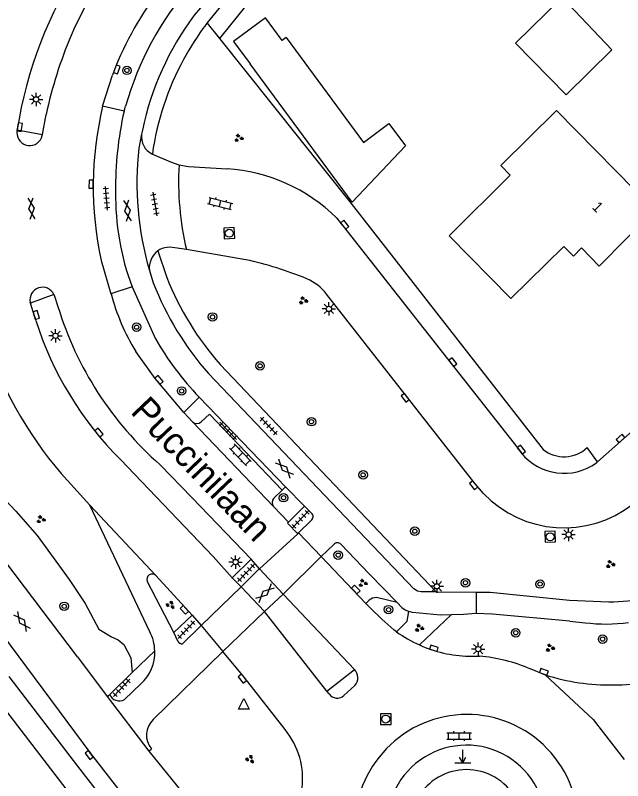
# Model space of a CAD drawing. Extents: x 137999 to 141000, y 397500 to 400501.
# Drawn here: x 138129 to 138186.2, y 398691.6 to 398763.7 of the extents above; entities that cross this region are included whole.
import ezdxf

# ---------------------------------------------------------------- set-up
doc = ezdxf.new("R2010")
doc.units = 0
for name, color, linetype in [('gg-afsc-erfafscheiding', 7, 'Continuous'), ('gg-anno-huisnummerreeks BGT', 7, 'Continuous'), ('gg-anno-openbare ruimte label', 7, 'Continuous'), ('gg-bbg-gedigitaliseerde bijgebouw', 7, 'Continuous'), ('gg-bbg-hoofdgebouw', 7, 'Continuous'), ('gg-knt-bronhoudergrens', 7, 'Continuous'), ('gg-knt-verharding', 7, 'Continuous'), ('gg-knt-verharding nz', 7, 'Continuous'), ('gt-grn-groengrens', 7, 'Continuous'), ('gt-grn-weggrens', 7, 'Continuous'), ('gt-symb-boom', 7, 'Continuous'), ('gt-symb-gesloten verharding', 7, 'Continuous'), ('gt-symb-groenvak', 7, 'Continuous'), ('gt-symb-klinker verharding', 7, 'Continuous'), ('gt-symb-kolk', 7, 'Continuous'), ('gt-symb-lichtmast', 7, 'Continuous'), ('gt-symb-markant object', 7, 'Continuous'), ('gt-symb-rioolschacht', 7, 'Continuous'), ('gt-symb-tegel verharding', 7, 'Continuous'), ('gt-symb-waterafsluiter', 7, 'Continuous')]:
    doc.layers.add(name, color=color, linetype=linetype)

# ---------------------------------------------------------------- blocks, each defined once
blk = doc.blocks.new('gt0-KOLK')
at = {"layer": 'gt-symb-kolk'}
blk.add_lwpolyline([(0, 0), (0.375, 0), (0.375, 0.4), (-0.375, 0.4), (-0.375, 0), (0, 0)], dxfattribs=at)
blk = doc.blocks.new('gt0-BOOM')
at = {"layer": 'gt-symb-boom'}
for radius in [0.4, 0.2]:
    blk.add_circle((0, 0), radius, dxfattribs=at)
blk = doc.blocks.new('gt0-LMAST')
at = {"layer": 'gt-symb-lichtmast'}
for p, q in [((-0.182, 0.173), (-0.447, 0.438)), ((-0.005, 0.246), (-0.005, 0.621)), ((0.172, 0.173), (0.437, 0.438)), ((-0.255, -0.004), (-0.63, -0.004)), ((-0.182, -0.181), (-0.447, -0.446)), ((-0.005, -0.254), (-0.005, -0.629)), ((0.437, -0.446), (0.172, -0.181)), ((0.245, -0.004), (0.62, -0.004))]:
    blk.add_line(p, q, dxfattribs=at)
blk.add_circle((-0.005, -0.004), 0.25, dxfattribs=at)
blk = doc.blocks.new('gt0-GESVH1')
at = {"layer": 'gt-symb-gesloten verharding'}
for p, q in [((-0.992, -0.261), (0.008, 0.239)), ((0.008, -0.261), (-0.992, 0.239)), ((0.008, 0.239), (1.008, -0.261)), ((1.008, 0.239), (0.008, -0.261))]:
    blk.add_line(p, q, dxfattribs=at)
blk = doc.blocks.new('gt0-TEG1')
at = {"layer": 'gt-symb-tegel verharding'}
for p, q in [((-1.125, 0), (1.125, 0)), ((-0.9, -0.25), (-0.9, 0.25)), ((-0.45, -0.25), (-0.45, 0.25)), ((0, -0.25), (0, 0.25)), ((0.45, -0.25), (0.45, 0.25)), ((0.9, -0.25), (0.9, 0.25))]:
    blk.add_line(p, q, dxfattribs=at)
blk = doc.blocks.new('gt0-KL1')
at = {"layer": 'gt-symb-klinker verharding'}
for p, q in [((-1.15, 0.3), (1.15, 0.3)), ((-1, -0.3), (-1, 0.3)), ((-0.5, 0.3), (-0.5, 0.45)), ((0, -0.3), (0, 0.3)), ((0.5, 0.3), (0.5, 0.45)), ((1, -0.3), (1, 0.3)), ((-1.15, -0.3), (1.15, -0.3)), ((-0.5, -0.45), (-0.5, -0.3)), ((0.5, -0.45), (0.5, -0.3))]:
    blk.add_line(p, q, dxfattribs=at)
blk = doc.blocks.new('gt0-RS')
at = {"layer": 'gt-symb-rioolschacht'}
blk.add_lwpolyline([(-0.5, -0.5), (0.5, -0.5), (0.5, 0.5), (-0.5, 0.5)], close=True, dxfattribs=at)
blk.add_circle((0, 0), 0.375, dxfattribs=at)
blk = doc.blocks.new('gt0-GRVAK')
at = {"layer": 'gt-symb-groenvak'}
for p, q in [((-0.11, 0.189), (-0.228, 0.24)), ((-0.182, 0.153), (0.088, 0.153)), ((-0.091, 0.211), (-0.156, 0.322)), ((-0.047, 0.214), (-0.047, 0.393)), ((-0.004, 0.211), (0.061, 0.322)), ((0.015, 0.189), (0.133, 0.24)), ((0.262, -0.052), (0.197, 0.059)), ((0.305, -0.049), (0.305, 0.13)), ((0.349, -0.052), (0.414, 0.059)), ((-0.245, -0.228), (-0.363, -0.177)), ((-0.318, -0.264), (-0.047, -0.264)), ((-0.226, -0.206), (-0.291, -0.095)), ((-0.183, -0.203), (-0.183, -0.024)), ((-0.139, -0.206), (-0.074, -0.095)), ((-0.12, -0.228), (-0.002, -0.177)), ((0.243, -0.074), (0.125, -0.023)), ((0.17, -0.11), (0.441, -0.11)), ((0.368, -0.074), (0.486, -0.023))]:
    blk.add_line(p, q, dxfattribs=at)
blk = doc.blocks.new('gt0-WAFSL')
at = {"layer": 'gt-symb-waterafsluiter'}
for p, q in [((-0.5, -0.333), (0, 0.667)), ((0, 0.667), (0.5, -0.333)), ((0.5, -0.333), (-0.5, -0.333))]:
    blk.add_line(p, q, dxfattribs=at)
blk = doc.blocks.new('gt0-MARKOB')
at = {"layer": 'gt-symb-markant object'}
for p, q in [((0, 0), (0, 1.2)), ((-0.75, 0), (0.75, 0)), ((0, 0), (-0.3, 0.52)), ((0, 0), (0.3, 0.52))]:
    blk.add_line(p, q, dxfattribs=at)

msp = doc.modelspace()

# ---------------------------------------------------------------- linework, layer by layer
at = {"layer": 'gg-afsc-erfafscheiding'}
for p, q in [((138147.036, 398762.936), (138148.205, 398761.472)), ((138139.751, 398683.118), (138127.758, 398698.679))]:
    msp.add_line(p, q, dxfattribs=at)
msp.add_lwpolyline([(138148.205, 398761.472), (138160.59, 398745.962), (138178.669, 398722.813)], dxfattribs=at)
msp.add_arc((138180.652, 398725.311), 3.19, 231.55041, 313.15167, dxfattribs=at)
at = {"layer": 'gg-bbg-gedigitaliseerde bijgebouw'}
for points in [[(138176.073, 398761.049), (138180.478, 398765.389), (138185.147, 398760.429), (138180.853, 398756.198), (138176.073, 398761.049)], [(138154.488, 398761.585), (138154.105, 398761.302), (138152.534, 398763.431), (138149.534, 398761.217), (138151.105, 398759.088)], [(138154.488, 398761.585), (138161.773, 398751.714), (138164.162, 398753.477), (138165.711, 398751.379), (138160.7, 398746.088), (138151.105, 398759.088)]]:
    msp.add_lwpolyline(points, dxfattribs=at)
at = {"layer": 'gg-bbg-hoofdgebouw'}
msp.add_lwpolyline([(138174.691, 398749.52), (138175.561, 398748.61), (138169.821, 398742.92), (138175.631, 398737.01), (138180.611, 398741.92), (138181.521, 398741), (138182.291, 398741.78), (138183.961, 398740.07), (138189.161, 398745.32), (138179.931, 398754.71), (138174.691, 398749.52)], dxfattribs=at)
at = {"layer": 'gg-knt-bronhoudergrens'}
msp.add_lwpolyline([(138178.867, 398701.608), (138183.382, 398697.392), (138186.297, 398693.634)], dxfattribs=at)
at = {"layer": 'gg-knt-verharding'}
for p, q in [((138147.036, 398762.936), (138158.71, 398777.157)), ((138146.405, 398764.369), (138145.831, 398763.67)), ((138146.939, 398762.818), (138147.036, 398762.936)), ((138138.441, 398758.882), (138138.13, 398758.048)), ((138137.202, 398755.105), (138138.13, 398758.048)), ((138139.217, 398754.64), (138137.202, 398755.105)), ((138139.217, 398754.64), (138139.361, 398755.13)), ((138131.527, 398752.458), (138131.871, 398754.323)), ((138129.14, 398752.86), (138129.145, 398752.892)), ((138129.145, 398752.892), (138131.527, 398752.458)), ((138140.951, 398752.862), (138140.868, 398752.48)), ((138131.511, 398752.37), (138131.527, 398752.458)), ((138140.868, 398752.48), (138140.619, 398751.17)), ((138130.001, 398751.46), (138130.191, 398751.42)), ((138142.387, 398741.503), (138143.231, 398738.979)), ((138145.09, 398741.62), (138144.217, 398741.738)), ((138150.682, 398740.665), (138145.09, 398741.62)), ((138137.069, 398740.601), (138137.987, 398737.466)), ((138141.601, 398739.663), (138141.971, 398738.48)), ((138139.973, 398738.111), (138137.987, 398737.466)), ((138139.973, 398738.111), (138142.135, 398733.283)), ((138132.617, 398737.397), (138130.393, 398736.582)), ((138132.651, 398737.32), (138132.991, 398736.277)), ((138130.393, 398736.582), (138130.368, 398736.661)), ((138130.901, 398734.96), (138130.393, 398736.582)), ((138200.091, 398736.162), (138183.801, 398721.645)), ((138148.251, 398730.81), (138168.611, 398709.394)), ((138144.83, 398726.288), (138146.277, 398727.74)), ((138154.421, 398719.282), (138146.277, 398727.74)), ((138134.84, 398703.296), (138116.908, 398726.868)), ((138144.83, 398726.288), (138145.646, 398725.415)), ((138145.646, 398725.415), (138153.295, 398717.425)), ((138147.592, 398712.743), (138138.876, 398721.865)), ((138142.621, 398721.37), (138145.591, 398718.273)), ((138183.801, 398721.645), (138183.69, 398721.546)), ((138133.299, 398720.532), (138135.996, 398717.562)), ((138154.088, 398718.992), (138153.327, 398718.211)), ((138154.088, 398718.992), (138154.421, 398719.282)), ((138156.216, 398717.46), (138154.421, 398719.282)), ((138151.172, 398712.474), (138145.591, 398718.273)), ((138141.641, 398705.65), (138135.996, 398717.562)), ((138154.693, 398715.97), (138153.295, 398717.425)), ((138156.216, 398717.46), (138154.693, 398715.97)), ((138156.873, 398716.818), (138156.216, 398717.46)), ((138155.655, 398714.97), (138156.83, 398716.116)), ((138155.563, 398714.88), (138155.655, 398714.97)), ((138157.785, 398712.726), (138158.957, 398713.871)), ((138147.592, 398712.743), (138149.402, 398710.74)), ((138151.172, 398712.474), (138149.402, 398710.74)), ((138151.982, 398711.571), (138151.172, 398712.474)), ((138161.996, 398708.318), (138157.785, 398712.726)), ((138143.893, 398705.587), (138141.401, 398710.406)), ((138142.214, 398710.946), (138145.624, 398707.2)), ((138149.402, 398710.74), (138150.241, 398709.863)), ((138152.452, 398707.561), (138154.193, 398709.184)), ((138154.193, 398709.184), (138160.902, 398702.106)), ((138168.611, 398709.394), (138172.369, 398709.376)), ((138158.318, 398700.062), (138152.452, 398707.561)), ((138143.893, 398705.587), (138145.624, 398707.2)), ((138145.624, 398707.2), (138146.485, 398706.25)), ((138146.485, 398706.25), (138144.718, 398704.522)), ((138181.191, 398706.636), (138182.632, 398706.5)), ((138144.287, 398704.78), (138143.893, 398705.587)), ((138142.111, 398703.851), (138139.992, 398701.801)), ((138141.949, 398697.388), (138148.517, 398703.793)), ((138134.84, 398703.296), (138137.621, 398699.553)), ((138171.659, 398703.35), (138172.67, 398703.355)), ((138139.992, 398701.801), (138137.873, 398699.75)), ((138158.318, 398700.062), (138160.902, 398702.106)), ((138177.504, 398702.145), (138178.867, 398701.608)), ((138139.253, 398699.275), (138140.787, 398700.745)), ((138160.945, 398700.588), (138159.925, 398699.638)), ((138137.621, 398699.553), (138137.873, 398699.75)), ((138158.528, 398699.794), (138158.318, 398700.062)), ((138141.554, 398694.421), (138141.792, 398694.637))]:
    msp.add_line(p, q, dxfattribs=at)
for points in [[(138141.883, 398750.614), (138143.6, 398749.879), (138144.39, 398749.587)], [(138144.39, 398749.587), (138145.279, 398749.435), (138148.915, 398749.228)], [(138159.217, 398744.601), (138159.849, 398743.83), (138170.017, 398730.902), (138176.623, 398722.475)], [(138173.053, 398718.657), (138172.291, 398719.567), (138158.293, 398737.433)], [(138144.83, 398726.288), (138142.131, 398729.49), (138140.331, 398732.03)], [(138168.611, 398709.394), (138167.191, 398709.4), (138166.831, 398709.47), (138166.501, 398709.69), (138147.169, 398729.952)], [(138154.088, 398718.992), (138147.274, 398726.133), (138146.484, 398725.407)], [(138154.693, 398715.97), (138154.611, 398715.878), (138155.563, 398714.88)], [(138164.937, 398708.396), (138162.3, 398711.113), (138159.642, 398713.881)], [(138150.241, 398709.863), (138151.873, 398711.505), (138151.982, 398711.571)], [(138172.369, 398709.376), (138173.681, 398709.37), (138181.161, 398708.61), (138184.861, 398708.47)], [(138164.881, 398705.639), (138164.629, 398705.826), (138163.499, 398706.827), (138162.415, 398707.875), (138161.996, 398708.318)], [(138164.937, 398708.396), (138165.384, 398707.936), (138165.681, 398707.718), (138166.016, 398707.552)], [(138170.026, 398707.237), (138169.018, 398707.216), (138166.372, 398707.448), (138166.016, 398707.552)], [(138172.359, 398707.368), (138171.182, 398707.261), (138170.026, 398707.237)], [(138181.191, 398706.636), (138173.898, 398707.3), (138172.359, 398707.368)], [(138127.784, 398705.356), (138136.093, 398694.176), (138143.936, 398684.05), (138144.646, 398683.101), (138144.718, 398682.997)], [(138154.383, 398696.443), (138150.514, 398701.365), (138148.517, 398703.793)], [(138141.477, 398684.453), (138134.874, 398692.99), (138128.386, 398701.442)], [(138141.554, 398694.421), (138146.299, 398688.563), (138148.875, 398686.4)]]:
    msp.add_lwpolyline(points, dxfattribs=at)
for centre, radius, start, end in [((138261.398, 398663.891), 170.81, 133.67131, 144.97275), ((138245.444, 398679.061), 150.927, 135.31184, 149.75881), ((138171.451, 398745.129), 40.78, 136.0715, 155.91278), ((138169.177, 398746.531), 40.534, 146.98222, 170.97108), ((138170.659, 398745.364), 34.939, 142.36329, 157.23873), ((138167.914, 398747.037), 29.678, 139.04988, 164.17548), ((138167.392, 398747.429), 26.993, 143.01082, 168.38917), ((138168.123, 398746.906), 26.494, 143.08779, 151.56828), ((138174.397, 398744.997), 43.537, 157.33686, 167.63041), ((138168.159, 398746.875), 26.541, 151.54838, 171.90241), ((138168.813, 398747.563), 32.498, 166.57988, 192.36936), ((138170.569, 398747.521), 32.15, 167.20732, 180.7865), ((138130.361, 398752.646), 1.24, 170.06751, 253.11552), ((138130.34, 398752.605), 1.195, 262.84726, 348.63764), ((138169.46, 398747.836), 29.033, 173.40571, 196.34983), ((138172.222, 398748.018), 27.876, 176.77379, 193.26871), ((138147.878, 398733.137), 16.124, 45.31356, 86.3133), ((138162.883, 398746.691), 24.464, 179.08985, 200.53229), ((138143.559, 398739.622), 2.216, 72.71212, 121.9231), ((138143.581, 398707.839), 33.586, 67.50138, 77.79398), ((138168.689, 398748.917), 28.684, 201.33746, 221.38896), ((138170.087, 398749.855), 28.975, 202.04764, 221.09533), ((138154.489, 398734.425), 4.849, 38.33175, 66.36749), ((138131.542, 398736.878), 1.194, 25.77146, 190.47059), ((138131.651, 398736.925), 1.075, 21.58043, 26.06809), ((138157.604, 398742.701), 20.303, 194.94294, 211.70841), ((138163.841, 398745.642), 32.241, 196.88713, 228.83822), ((138161.823, 398744.816), 32.455, 197.6791, 225.00466), ((138161.72, 398744.895), 37.434, 197.51375, 220.60438), ((138167.073, 398747.599), 28.755, 209.85835, 223.6794), ((138146.069, 398725.835), 0.596, 224.81026, 314.09582), ((138180.649, 398725.755), 5.193, 219.1744, 305.84773), ((138153.728, 398717.801), 0.574, 134.37134, 220.96593), ((138180.638, 398725.973), 10.538, 223.96857, 308.01701), ((138156.56, 398716.485), 0.457, 306.22327, 46.76635), ((138159.304, 398713.566), 0.462, 42.96262, 138.71013), ((138141.872, 398710.579), 0.502, 46.97516, 200.2096), ((138184.893, 398725.83), 17.36, 269.8932, 293.58436), ((138184.552, 398721.609), 15.23, 262.75956, 278.11345), ((138137.95, 398703.725), 4.163, 1.73792, 27.54531), ((138171.976, 398715.49), 12.14, 234.23617, 245.89959), ((138144.659, 398704.913), 0.395, 199.61403, 278.57583), ((138138.248, 398703.663), 3.868, 311.03384, 2.7918), ((138171.985, 398715.485), 12.14, 245.85119, 268.45917), ((138171.331, 398687.743), 15.669, 66.79743, 85.09662), ((138160.154, 398701.325), 1.081, 317.0051, 46.24004), ((138185.112, 398720.804), 20.163, 270.58229, 289.01327), ((138184.966, 398720.315), 19.676, 251.94248, 271.02205), ((138138.772, 398700.119), 0.972, 202.33709, 299.67568), ((138159.3, 398700.372), 0.964, 216.82247, 310.43413), ((138143.358, 398695.928), 2.029, 133.96625, 219.50107), ((138171.496, 398687.354), 10.513, 49.93427, 141.83926), ((138148.715, 398691.815), 7.317, 352.44569, 39.2338), ((138171.395, 398687.303), 10.617, 315.60101, 49.69484), ((138171.468, 398687.448), 7.527, 63.32257, 187.89072), ((138171.389, 398687.335), 10.441, 141.39444, 229.88588), ((138171.299, 398687.363), 7.68, 299.60008, 62.48116)]:
    msp.add_arc(centre, radius, start, end, dxfattribs=at)
at = {"layer": 'gg-knt-verharding nz'}
for p, q in [((138135.996, 398717.562), (138142.214, 398710.946)), ((138157.785, 398712.726), (138155.655, 398714.97)), ((138154.193, 398709.184), (138151.982, 398711.571)), ((138150.241, 398709.863), (138152.452, 398707.561)), ((138146.485, 398706.25), (138148.517, 398703.793))]:
    msp.add_line(p, q, dxfattribs=at)
for centre, radius, start, end in [((138142.628, 398752.228), 1.778, 171.856, 245.23145), ((138143.642, 398739.879), 2.052, 127.69141, 186.04677)]:
    msp.add_arc(centre, radius, start, end, dxfattribs=at)
at = {"layer": 'gt-grn-groengrens'}
for p, q in [((138183.801, 398721.645), (138182.834, 398722.984)), ((138167.019, 398704.408), (138170.026, 398707.237))]:
    msp.add_line(p, q, dxfattribs=at)
for points in [[(138159.339, 398776.647), (138159.96, 398776.143), (138148.205, 398761.472)], [(138116.908, 398726.868), (138118.211, 398727.734), (138119.414, 398728.115), (138120.232, 398728.182), (138121.551, 398727.757), (138122.277, 398727.014), (138126.177, 398720.393), (138127.5, 398718.611), (138129.04, 398716.992), (138131.023, 398714.71), (138134.037, 398710.565), (138135.542, 398708.31), (138136.843, 398705.887), (138138.025, 398705.17), (138138.661, 398704.902), (138139.208, 398704.453), (138139.847, 398703.2), (138139.992, 398701.801)], [(138164.937, 398708.396), (138162.988, 398708.882), (138162.62, 398708.808), (138162.302, 398708.608), (138161.996, 398708.318)], [(138164.881, 398705.639), (138165.879, 398706.648), (138166.016, 398707.552)]]:
    msp.add_lwpolyline(points, dxfattribs=at)
msp.add_arc((138171.467, 398687.379), 5.295, 359.99458, 180.00542, dxfattribs=at)
at = {"layer": 'gt-grn-weggrens'}
for p, q in [((138155.563, 398714.88), (138151.982, 398711.571)), ((138154.193, 398709.184), (138157.785, 398712.726)), ((138150.241, 398709.863), (138146.485, 398706.25)), ((138172.369, 398709.376), (138172.359, 398707.368)), ((138148.517, 398703.793), (138152.452, 398707.561)), ((138137.621, 398699.553), (138141.554, 398694.421))]:
    msp.add_line(p, q, dxfattribs=at)

# ---------------------------------------------------------------- block references
at = {"layer": 'gt-symb-boom'}
for p in [(138139.487, 398758.484), (138147.546, 398735.282), (138140.4, 398734.316), (138152.023, 398730.677), (138144.64, 398728.313), (138156.863, 398725.419), (138161.728, 398720.419), (138154.234, 398718.263), (138166.593, 398715.116), (138159.38, 398712.86), (138171.362, 398710.262), (138178.387, 398710.143), (138133.585, 398708.045), (138164.12, 398707.731), (138176.093, 398705.556), (138184.273, 398704.96)]:
    msp.add_blockref('gt0-BOOM', p, dxfattribs=at)
at = {"layer": 'gt-symb-gesloten verharding'}
for p, rotation in [((138130.494, 398745.473), 94.99208116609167), ((138139.552, 398745.292), -82.70443985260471), ((138154.315, 398720.998), 134.02760489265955), ((138152.507, 398709.278), -136.9861065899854), ((138129.599, 398706.595), 126.99589776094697)]:
    msp.add_blockref('gt0-GESVH1', p, dxfattribs=dict(at, rotation=rotation))
at = {"layer": 'gt-symb-groenvak'}
for p in [(138150.006, 398752.11), (138156.08, 398736.821), (138131.373, 398716.216), (138184.998, 398712.004), (138161.692, 398710.225), (138167.003, 398706.007), (138179.317, 398704.127)]:
    msp.add_blockref('gt0-GRVAK', p, dxfattribs=at)
for p, rotation in [((138143.582, 398708.187), -39.11608917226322), ((138151.069, 398693.672), -39.15225868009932)]:
    msp.add_blockref('gt0-GRVAK', p, dxfattribs=dict(at, rotation=rotation))
at = {"layer": 'gt-symb-klinker verharding'}
for p, rotation in [((138148.27, 398745.953), -14.119602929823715), ((138150.174, 398722.304), 134.02760489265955)]:
    msp.add_blockref('gt0-KL1', p, dxfattribs=dict(at, rotation=rotation))
msp.add_blockref('gt0-KL1', (138170.765, 398695.849), dxfattribs=at)
at = {"layer": 'gt-symb-kolk'}
for p, rotation in [((138138.354, 398758.647), -111.2739051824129), ((138129.192, 398753.169), -99.2645239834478), ((138136.315, 398747.766), 89.63686259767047), ((138159.849, 398743.83), -50.68106918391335), ((138130.759, 398735.416), -72.59811208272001), ((138170.017, 398730.902), -51.81784506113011), ((138142.353, 398729.222), -49.90831919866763), ((138165.844, 398727.793), 128.08379432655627), ((138136.694, 398724.28), -50.597758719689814), ((138186.094, 398723.686), 41.67710007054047), ((138176.472, 398722.661), -51.9325118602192), ((138172.291, 398719.567), 129.96055821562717), ((138160.886, 398709.49), -46.215428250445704), ((138145.041, 398707.841), 132.3238165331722), ((138168.329, 398703.909), -17.511195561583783), ((138150.514, 398701.365), 129.43862478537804), ((138178.671, 398701.695), -21.09921225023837), ((138136.093, 398694.176), 127.72926989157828)]:
    msp.add_blockref('gt0-KOLK', p, dxfattribs=dict(at, rotation=rotation))
at = {"layer": 'gt-symb-lichtmast'}
for p in [(138130.937, 398755.756), (138158.511, 398736.037), (138132.768, 398733.503), (138181.081, 398714.796), (138149.722, 398712.212), (138168.671, 398709.93), (138172.571, 398704.02)]:
    msp.add_blockref('gt0-LMAST', p, dxfattribs=at)
at = {"layer": 'gt-symb-markant object'}
msp.add_blockref('gt0-MARKOB', (138171.102, 398693.322), dxfattribs=at)
at = {"layer": 'gt-symb-rioolschacht'}
for p, rotation in [((138149.123, 398743.16), -87.18232907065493), ((138179.337, 398714.597), 1.6868195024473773)]:
    msp.add_blockref('gt0-RS', p, dxfattribs=dict(at, rotation=rotation))
msp.add_blockref('gt0-RS', (138163.856, 398697.434), dxfattribs=at)
at = {"layer": 'gt-symb-tegel verharding'}
for p, rotation in [((138137.568, 398746.449), 94.644721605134), ((138142.114, 398745.912), -80.15137761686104), ((138149.009, 398724.564), -45.97239510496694), ((138152.833, 398725.013), -45.972395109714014), ((138155.842, 398716.238), 46.53940290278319), ((138150.711, 398711.195), 46.581010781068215), ((138145.076, 398705.846), 46.539402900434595), ((138139.003, 398700.374), 46.58101078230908)]:
    msp.add_blockref('gt0-TEG1', p, dxfattribs=dict(at, rotation=rotation))
at = {"layer": 'gt-symb-waterafsluiter'}
msp.add_blockref('gt0-WAFSL', (138150.499, 398698.696), dxfattribs=at)

# ---------------------------------------------------------------- texts
at = {"layer": 'gg-anno-huisnummerreeks BGT'}
msp.add_text('1', height=1, rotation=315.2, dxfattribs=at).set_placement((138183.207, 398745.546))
at = {"layer": 'gg-anno-openbare ruimte label'}
msp.add_text('Puccinilaan', height=2.5, rotation=313.7, dxfattribs=at).set_placement((138139.733, 398726.297))

doc.saveas('drawing.dxf')
